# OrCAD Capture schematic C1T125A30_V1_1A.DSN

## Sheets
1 002_others: size A4; title: Telink-Semi; rev: V1.1A; note: C1T125A30
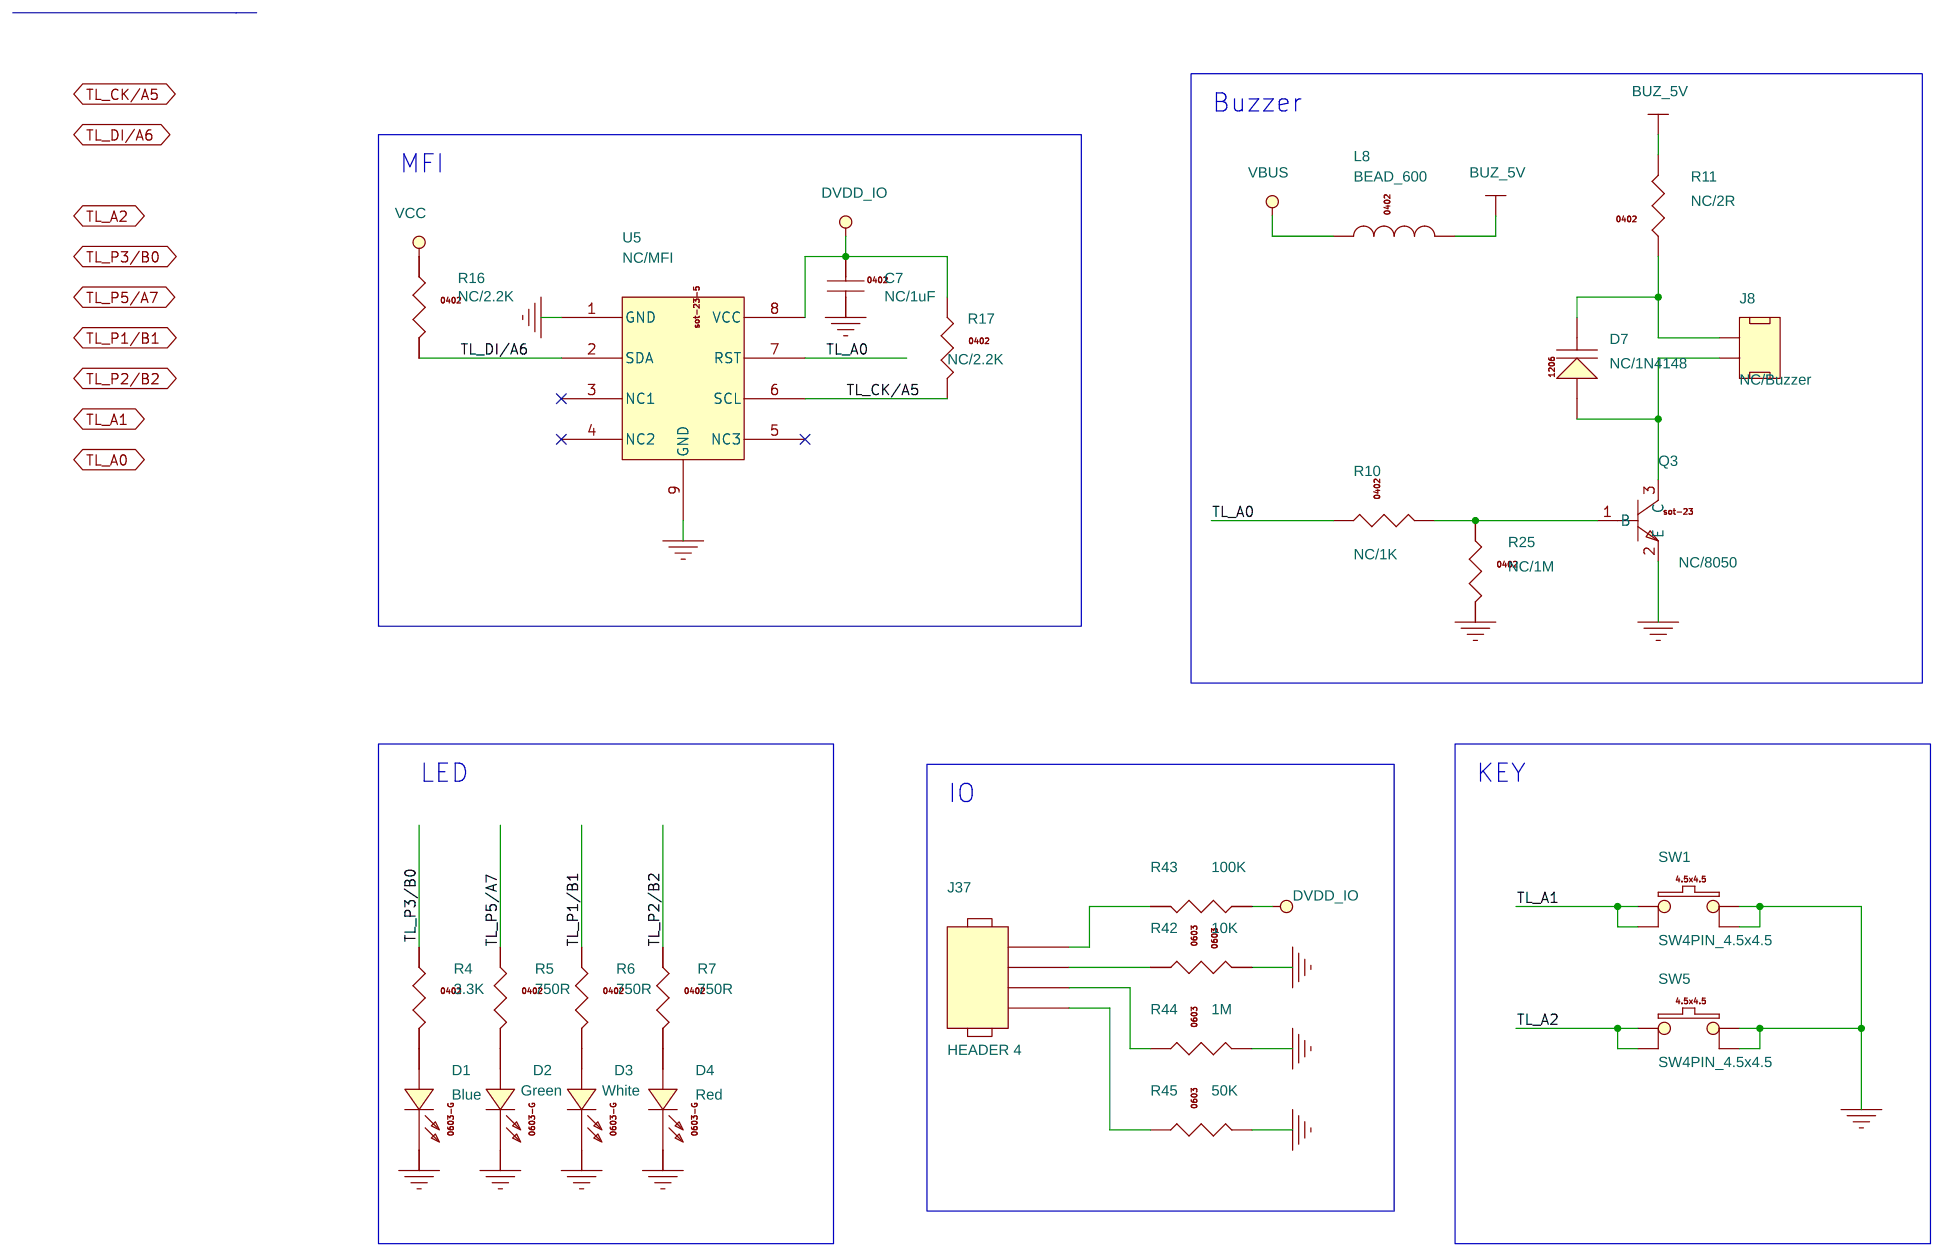
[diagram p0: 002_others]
2 001_main: size A4
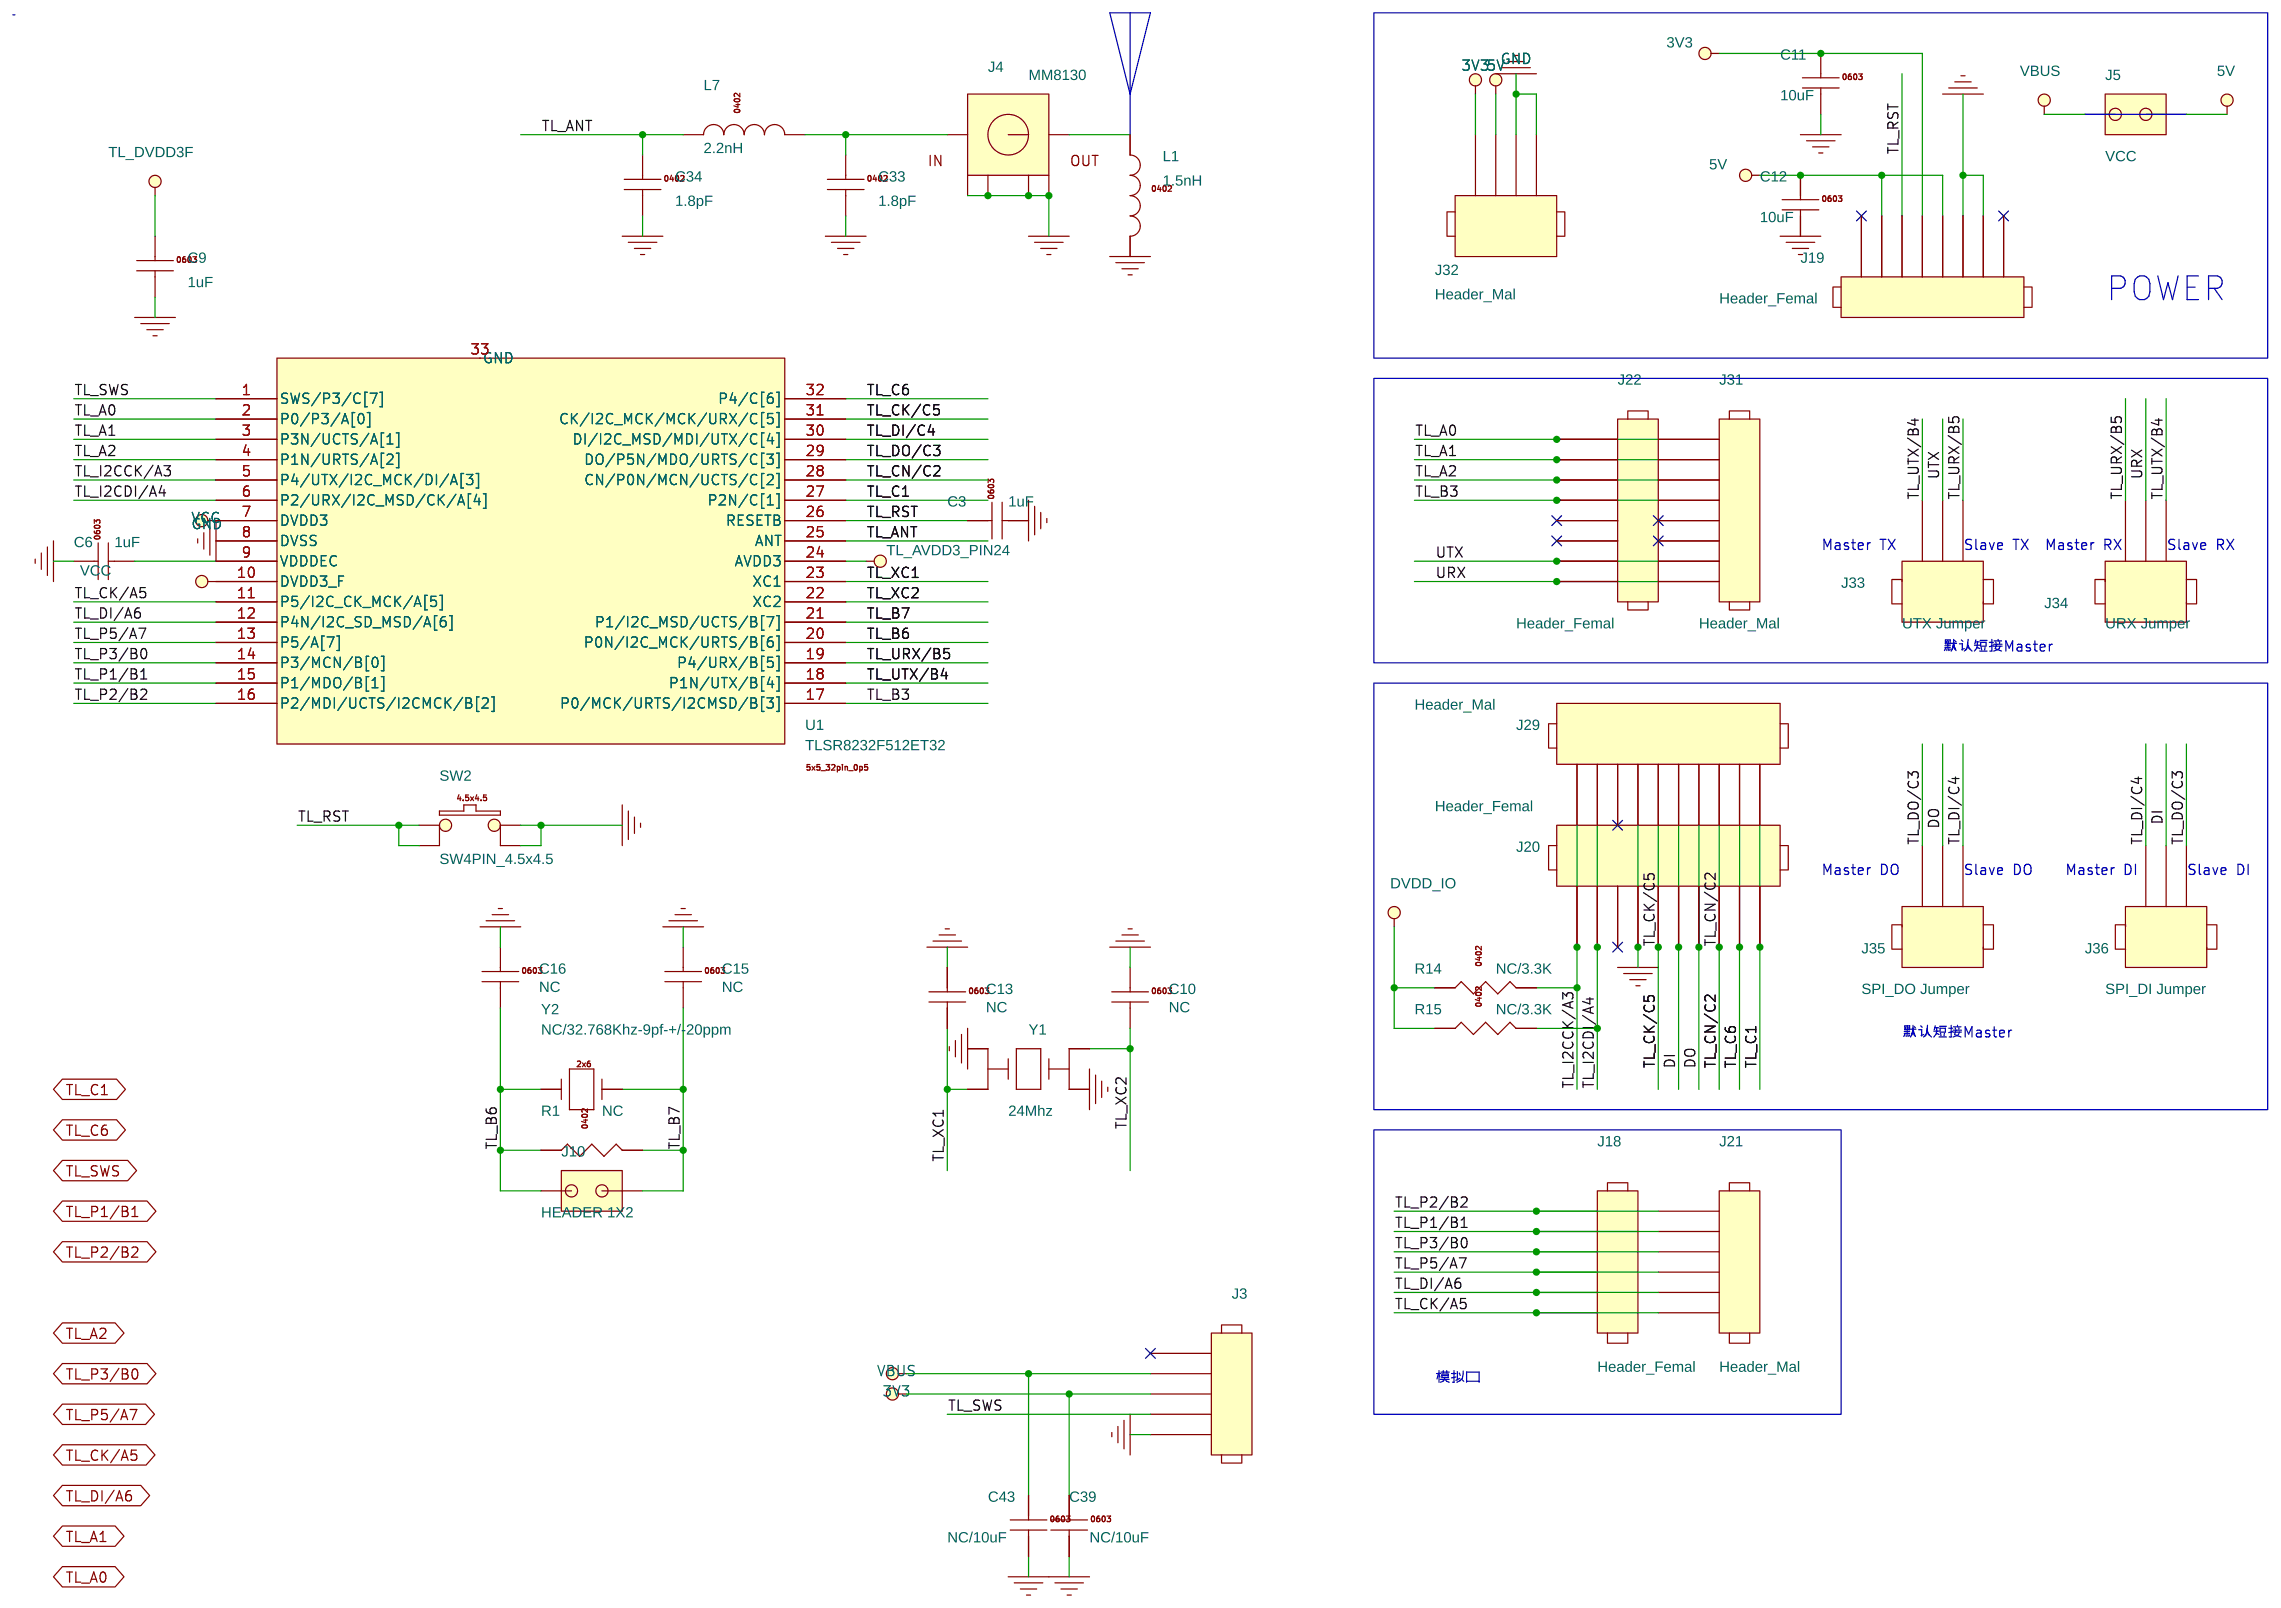
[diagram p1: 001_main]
3 003_power: size A4
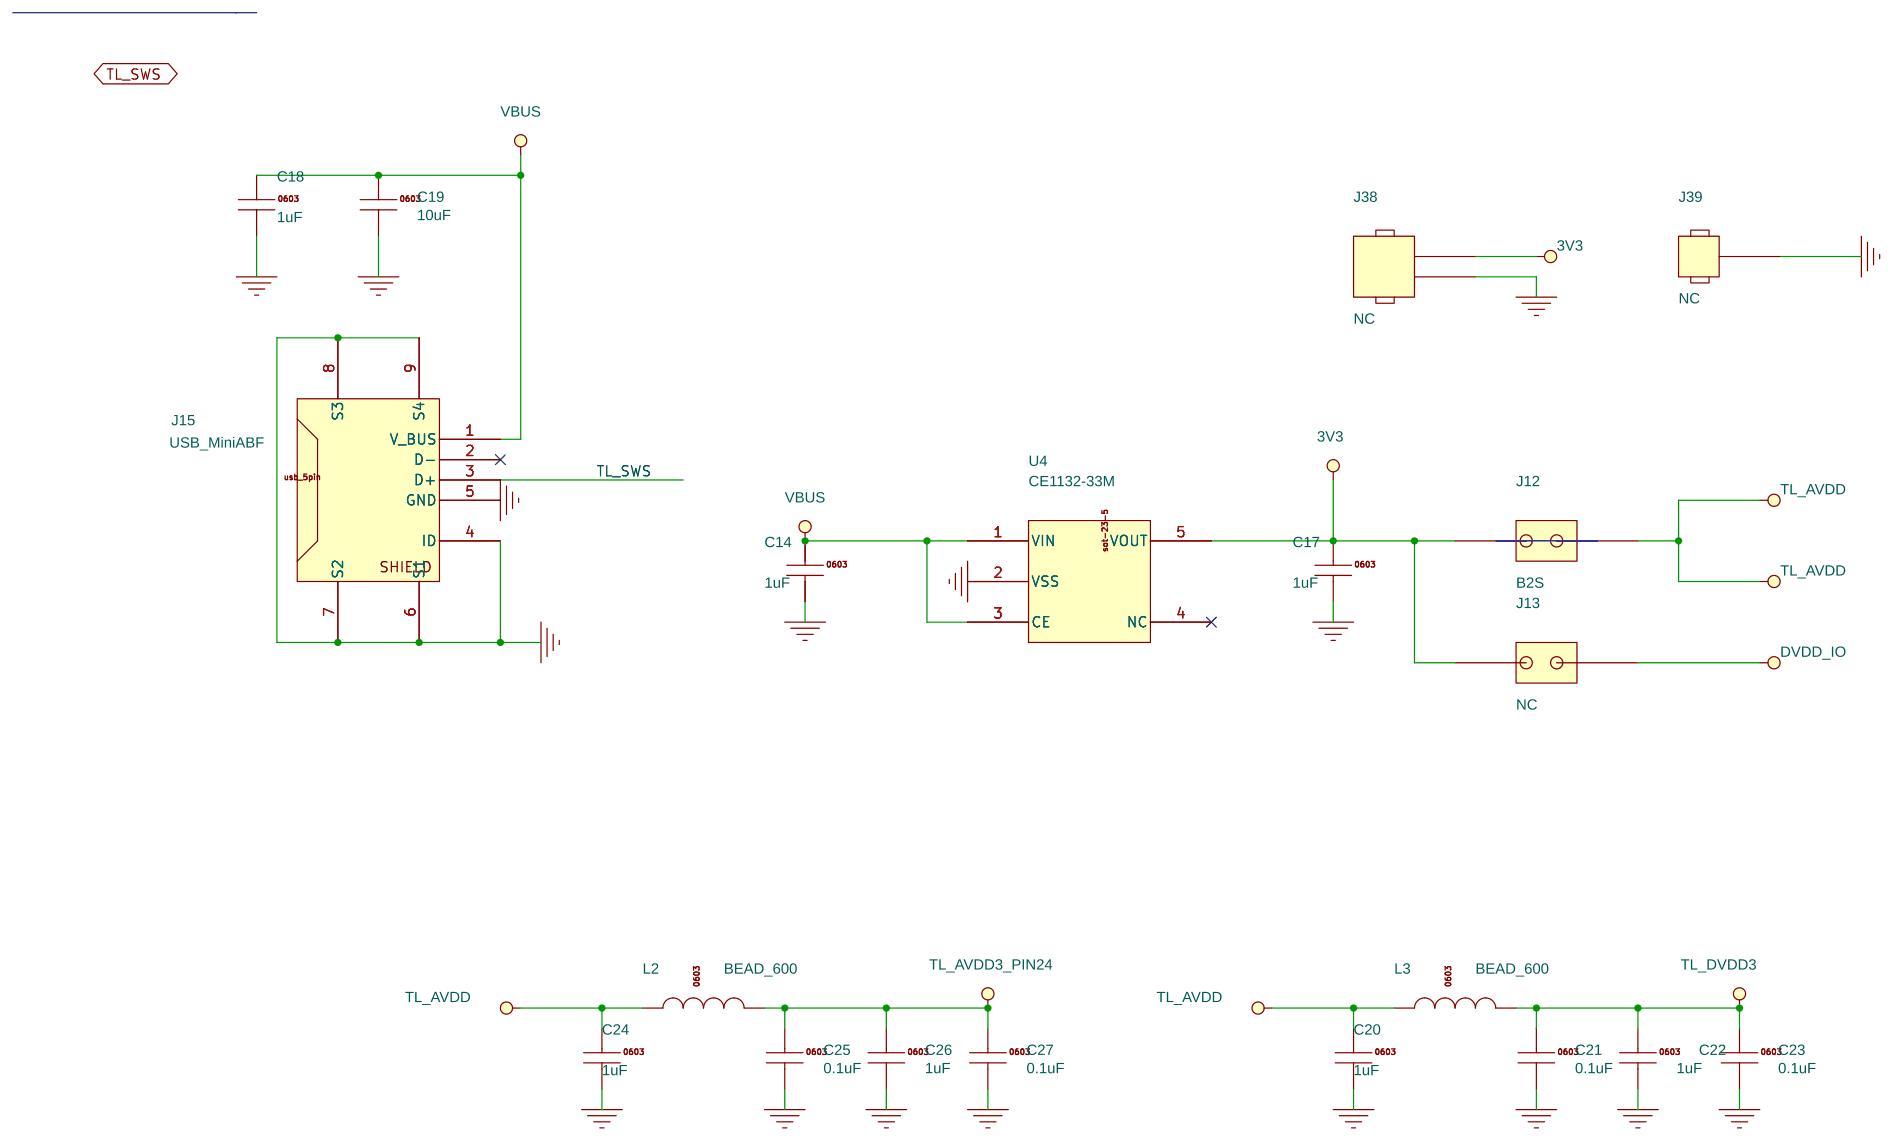
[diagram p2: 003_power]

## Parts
sheet 001_main
C3  1uF  [0603C1]
C6  1uF  [0603C1]
C9  1uF  [0603C1]
C10  NC  [0603C1]
C11  10uF  [0603C1]
C12  10uF  [0603C1]
C13  NC  [0603C1]
C15  NC  [0402]
C16  NC  [0402]
C33  1.8pF  [0402]
C34  1.8pF  [0402]
C39  NC/10uF  [0603C1]
C43  NC/10uF  [0603C1]
J3  HEADER 5  [HDR254F-1X5X850]
J4  MM8130  [MM8130-2600]
J5  VCC  [HDR254F-1X2X850]
J10  HEADER 1X2  [HDR254F-1X2X850]
J18  Header_Femal  [HDR254F-1X6X850]
J19  Header_Femal  [hdr254f-1x8x850]
J20  Header_Femal  [hdr254f-1x10x850]
J21  Header_Mal  [HDR254F-1X6X850]
J22  Header_Femal  [hdr254f-1x8x850]
J29  Header_Mal  [hdr254f-1x10x850]
J31  Header_Mal  [hdr254f-1x8x850]
J32  Header_Mal  [HDR254F-1X4X850]
J33  UTX Jumper  [HDR254F-1X3X850]
J34  URX Jumper  [HDR254F-1X3X850]
J35  SPI_DO Jumper  [HDR254F-1X3X850]
J36  SPI_DI Jumper  [HDR254F-1X3X850]
L1  1.5nH  [0402]
L7  2.2nH  [0402]
R1  NC  [0402]
R14  NC/3.3K  [0402]
R15  NC/3.3K  [0402]
SW2  SW4PIN_4.5x4.5  [BUTDIP4P_5P0X3P0]
U1  TLSR8232F512ET32  [qfn_5x5_32pin_0p5_2p50x2p50]
Y1  24Mhz  [osccc250x320x110]
Y2  NC/32.768Khz-9pf-+/-20ppm  [OSC_2x6]
sheet 002_others
C7  NC/1uF  [0402]
D1  Blue  [0603-LED]
D2  Green  [0603-LED]
D3  White  [0603-LED]
D4  Red  [0603-LED]
D7  NC/1N4148  [SOD80]
J8  NC/Buzzer  [BUZZER]
J37  HEADER 4  [HDR254F-1X4X850]
L8  BEAD_600  [0603L1]
Q3  NC/8050  [bjt_sot-23]
R4  3.3K  [0402]
R5  750R  [0402]
R6  750R  [0402]
R7  750R  [0402]
R10  NC/1K  [0402]
R11  NC/2R  [0402]
R16  NC/2.2K  [0402]
R17  NC/2.2K  [0402]
R25  NC/1M  [0402]
R42  10K  [0603R]
R43  100K  [0603R]
R44  1M  [0603R]
R45  50K  [0603R]
SW1  SW4PIN_4.5x4.5  [BUTDIP4P_5P0X3P0]
SW5  SW4PIN_4.5x4.5  [BUTDIP4P_5P0X3P0]
U5  NC/MFI  [cp]
sheet 003_power
C14  1uF  [0603C1]
C17  1uF  [0603C1]
C18  1uF  [0603C1]
C19  10uF  [0603C1]
C20  1uF  [0603C1]
C21  0.1uF  [0603C1]
C22  1uF  [0603C1]
C23  0.1uF  [0402]
C24  1uF  [0603C1]
C25  0.1uF  [0603C1]
C26  1uF  [0603C1]
C27  0.1uF  [0402]
J12  B2S  [hdr254f-1x2x850]
J13  NC  [hdr254f-1x2x850]
J15  USB_MiniABF  [USB-MINI-F5]
J38  NC  [HDR254F-1X2X850]
J39  NC  [HDR254F-1X1X850]
L2  BEAD_600  [0603L1]
L3  BEAD_600  [0603L1]
U4  CE1132-33M  [sot-23-5]

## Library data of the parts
C3 C6 C9 C14 C17 C18 C22 C26 = C1608X5R1C105M
C10 C13 C15 C16 = C1608_NC
C11 C12 C19 C20 C24 C39 C43 = C1608X5R0J106M
C33 C34 = C1005_NC
J3 = HEADER_5
J4 = MM8130
J5 J10 = B2S_3: PAGE: POWER
J18 J21 = HEADER_6
J19 J22 J31 = HEADER_8
J20 J29 = HEADER_10
J32 J37 = HEADER_4
J33-J36 = HEADER_3
L1 = MLK1005_000R
L7 = MLK1005S2N2ST
R1 = RS0402_NC
R14 R15 = RS0402K332JT
SW1 SW2 SW5 = SW4PIN_0.5
U1 = TLSR8232F512ET32
Y1 = CRYSTAL4_SM_0
Y2 = OSC_2x6_2pin
C7 = C1005X5R1C105K
D1-D4 = 0603D_Green
D7 = Diode_1N4148
J8 = CONN_MOD_8-2_J_0
L8 = MMZ1005Y601C
Q3 = NPN_C1815
R4-R7 R10 R11 R25 = RS0402K102JT
R16 R17 = RS0402K222JT
R42-R45 = RS0603K104JT
U5 = XC6219_3.3V_SOT-23-5
C21 C25 = C1608X5R1H104M
C23 C27 = C1608X5R1H103K
J12 J13 = B2S_0
J15 = USB_MiniABF_5pin
J38 = HEADER_2
J39 = HEADER_1
L2 L3 = MMZ1608Y601C
U4 = XC6219_0.3V_SOT-23-5

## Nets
3V3: C11.1 C17.1 C39.1 J3.3 J12.1 J13.1 J19.4 J32.1 J38.1 U4.5(VOUT)
5V: C12.1 J5.2 J19.2 J19.5 J32.2
DVDD_IO: C7.1 J13.2 R14.1 R15.1 R16.1 R17.1 R43.1 U5.8(VCC)
GND: C3.2 C6.1 C7.2 C9.2 C10.1 C11.2 C12.2 C13.1 C14.2 C15.1 C16.1 C17.2 C18.2 C19.2 C20.2 C21.2 C22.2 C23.2 C24.2 C25.2 C26.2 C27.2 C33.2 C34.2 C39.2 C43.2 D1.C(CATHODE) D2.C(CATHODE) D3.C(CATHODE) D4.C(CATHODE) J3.5 J4.3 J4.4 J4.5 J4.6 J15.4(ID) J15.5(GND) J15.6(S1) J15.7(S2) J15.8(S3) J15.9(S4) J19.6 J19.7 J20.4 J29.4 J32.3 J32.4 J38.2 J39.1 L1.2 Q3.2(E) R25.2 R42.2 R44.2 R45.2 SW1.2 SW1.4 SW2.2 SW2.4 SW5.2 SW5.4 U1.8(DVSS) U1.33(GND) U4.2(VSS) U5.1(GND) U5.9(GND) Y1.2 Y1.4
VBUS: C14.1 C18.1 C19.1 C43.1 J3.2 J5.1 J15.1(V_BUS) L8.1 U4.1(VIN) U4.3(CE)
Buz_5V: L8.2 R11.2
DI: J20.6 J29.6 J36.2
DO: J20.7 J29.7 J35.2
TL_A0: J22.1 J31.1 U1.2(P0/P3/A[0])
TL_A0 (page 002_others): R10.1 U5.7(RST)
TL_A1: J22.2 J31.2 U1.3(P3N/UCTS/A[1])
TL_A1 (page 002_others): SW1.1 SW1.3
TL_A2: J22.3 J31.3 U1.4(P1N/URTS/A[2])
TL_A2 (page 002_others): SW5.1 SW5.3
TL_ANT: C34.1 L7.1 U1.25(ANT)
TL_AVDD: C20.1 C24.1 J12.2 L2.1 L3.1
TL_AVDD3_PIN24: C25.1 C26.1 C27.1 L2.2 U1.24(AVDD3)
TL_B3: J22.4 J31.4 U1.17(P0/MCK/URTS/I2CMSD/B[3])
TL_B6: C16.2 J10.1 R1.1 U1.20(P0N/I2C_MCK/URTS/B[6]) Y2.1
TL_B7: C15.2 J10.2 R1.2 U1.21(P1/I2C_MSD/UCTS/B[7]) Y2.2
TL_C1: J20.10 J29.10 U1.27(P2N/C[1])
TL_C6: J20.9 J29.9 U1.32(P4/C[6])
TL_CK/A5: J18.6 J21.6 U1.11(P5/I2C_CK_MCK/A[5])
TL_CK/A5 (page 002_others): R17.2 U5.6(SCL)
TL_CK/C5: J20.5 J29.5 U1.31(CK/I2C_MCK/MCK/URX/C[5])
TL_CN/C2: J20.8 J29.8 U1.28(CN/P0N/MCN/UCTS/C[2])
TL_DI/A6: J18.5 J21.5 U1.12(P4N/I2C_SD_MSD/A[6])
TL_DI/A6 (page 002_others): R16.2 U5.2(SDA)
TL_DI/C4: J35.3 J36.1 U1.30(DI/I2C_MSD/MDI/UTX/C[4])
TL_DO/C3: J35.1 J36.3 U1.29(DO/P5N/MDO/URTS/C[3])
TL_DVDD3: C21.1 C22.1 C23.1 L3.2 U1.7(DVDD3)
TL_DVDD3F: C9.1 U1.10(DVDD3_F)
TL_I2CCK/A3: J20.1 J29.1 R14.2 U1.5(P4/UTX/I2C_MCK/DI/A[3])
TL_I2CDI/A4: J20.2 J29.2 R15.2 U1.6(P2/URX/I2C_MSD/CK/A[4])
TL_P1/B1: J18.2 J21.2 U1.15(P1/MDO/B[1])
TL_P1/B1 (page 002_others): R6.1
TL_P2/B2: J18.1 J21.1 U1.16(P2/MDI/UCTS/I2CMCK/B[2])
TL_P2/B2 (page 002_others): R7.1
TL_P3/B0: J18.3 J21.3 U1.14(P3/MCN/B[0])
TL_P3/B0 (page 002_others): R4.1
TL_P5/A7: J18.4 J21.4 U1.13(P5/A[7])
TL_P5/A7 (page 002_others): R5.1
TL_RST: C3.1 J19.3 SW2.1 SW2.3 U1.26(RESETB)
TL_SWS: J3.4 U1.1(SWS/P3/C[7])
TL_SWS (page 003_power): J15.3(D+)
TL_URX/B5: J33.3 J34.1 U1.19(P4/URX/B[5])
TL_UTX/B4: J33.1 J34.3 U1.18(P1N/UTX/B[4])
TL_XC1: C13.2 U1.23(XC1) Y1.3
TL_XC2: C10.2 U1.22(XC2) Y1.1
URX: J22.8 J31.8 J34.2
UTX: J22.7 J31.7 J33.2
N19433324: Q3.1(B) R10.2 R25.1
N19433336: D7.A J8.2 Q3.3(C)
N19433338: D7.C J8.1 R11.1
N19452982: C6.2 U1.9(VDDDEC)
N19453491: C33.1 J4.1 L7.2
N19453517: J4.2 L1.1
N19478014: D4.A(ANODE) R7.2
N19478016: D3.A(ANODE) R6.2
N19478024: D1.A(ANODE) R4.2
N19478026: D2.A(ANODE) R5.2
N19478691: J37.2 R42.1
N19478703: J37.3 R44.1
N19478721: J37.4 R45.1
N19478794: J37.1 R43.2

Not connected (* = marked no-connect by the designer): J3 1*; J15 2(D-)*; J19 1* 8*; J20 3*; J22 5* 6*; J29 3*; J31 5* 6*; U4 4(NC)*; U5 3(NC1)* 4(NC2)* 5(NC3)*

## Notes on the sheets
sheet 1
- Buzzer
- MFI
- LED
- KEY
- IO
sheet 2
- POWER
- Master TX
- Slave TX
- Master RX
- Slave RX
- 默认短接Master
- Master DO
- Slave DO
- Master DI
- Slave DI
- 默认短接Master
- 模拟口
